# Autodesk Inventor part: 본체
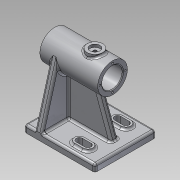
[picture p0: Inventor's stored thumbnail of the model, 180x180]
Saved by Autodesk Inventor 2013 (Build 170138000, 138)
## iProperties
Created: 2019-10
Part Number: 본체
Material: 알루미늄 6061
Document SubType Name: Modeling
Designer: hana-cad17
Density: 2.40731 g/cm^3
Mass: 523.177 g
Surface Area: 544.458 cm^2
Volume: 217.328 cm^3
Author: hana-cad17
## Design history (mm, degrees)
sketch "스케치1"
  geometry: L1 (-50, 43)-(50, 43); L2 (50, 43)-(50, -43); L3 (50, -43)-(-50, -43); L4 (-50, -43)-(-50, 43); 3 further points
  constraints: 8 end point, 2 midpoint, 2 parallel, 1 horizontal, 1 horizontal alignment, 1 perpendicular, 1 vertical alignment
  dimensions: "d0" = 100 distance of L1.start L1.end; "d2" = 86 distance of L3.end L1.start
extrude "돌출1" new body sketch "스케치1" distance "d3" = 10; taper "d4" = 0 deg
sketch "스케치2"
  geometry: L1 (-32, 86)-(50, 86); L2 (50, 0)-(-50, 0) reference; L3 (-32, 86)-(-32, 107); L4 (-32, 107)-(50, 107); L5 (50, 107)-(50, 86); L6 (50, 0)-(50, 10) reference; 2 further points
  constraints: 8 end point, 2 perpendicular, 1 horizontal, 1 midpoint, 1 parallel, 1 vertical alignment
  dimensions: "d5" = 82 distance of L1.start L1.end; "d7" = 86 distance from line of L1.end L2; "d8" = 42 diameter of L4 L1
revolve "회전1" sketch "스케치2" stored, may be unused: angle "d9" = 90 deg
sketch "스케치4"
  geometry: L1 (50, 65)-(50, 107) reference; L2 (-32, 65)-(-32, 107) reference; L3 (-32, 86)-(50, 86); L4 (-32, 100.5)-(30, 100.5); L5 (30, 100.5)-(30, 97.5); L6 (30, 97.5)-(50, 97.5); 1 further point
  constraints: 8 end point, 2 midpoint, 2 parallel, 2 point on line, 1 perpendicular
  dimensions: "d11" = 23 diameter of L6 L3; "d13" = 29 diameter of L4 L3; "d14" = 62 distance of L4.start L4.end
revolve "회전2" sketch "스케치4" stored, may be unused: angle "d15" = 90 deg
node "작업 평면1"
sketch "스케치6"
  geometry: L1 (0, 86)-(10, 86) reference; L2 (10, 86)-(10, 0) reference; L3 (10, 0)-(0, 0) reference; L4 (0, 0)-(0, 86) reference; L5 (10, 86)-(91.642, 63.228); L6 (10, 0)-(91.642, 22.772); C1 r 11.5 at (86, 43) reference; A1 r 21 centre (86, 43) between (91.642, 63.228) and (91.642, 22.772) reference; 1 further point
  constraints: 4 end point, 2 point on circle, 2 tangent
extrude "돌출2" join sketch "스케치6" distance "d19" = 10; taper "d20" = 0 deg
sketch "스케치7"
  geometry: L1 (50, 97.5)-(30, 97.5) reference; L2 (30, 97.5)-(30, 100.5) reference; L3 (30, 100.5)-(-32, 100.5) reference; L4 (-32, 100.5)-(-32, 107) reference; L5 (-32, 107)-(50, 107) reference; L6 (50, 107)-(50, 97.5) reference; L7 (-50, 0)-(-50, 10) reference; L8 (-50, 10)-(25, 10) reference; L9 (25, 10)-(25, 65) reference; L10 (25, 65)-(-32, 65) reference; L11 (-32, 65)-(-32, 71.5) reference; L12 (-32, 71.5)-(30, 71.5) reference; L13 (30, 71.5)-(30, 74.5) reference; L14 (30, 74.5)-(50, 74.5) reference; L15 (50, 74.5)-(50, 65) reference; L16 (50, 65)-(35, 65) reference; L17 (35, 65)-(35, 10) reference; L18 (35, 10)-(50, 10) reference; L19 (50, 10)-(50, 0) reference; L20 (50, 0)-(-50, 0) reference; L21 (-35, 10)-(-14.982, 65); 1 further point
  constraints: 2 end point, 2 point on line
  dimensions: "d21" = 70 deg angle of L21 L8; "d22" = 15 distance of L7.end L21.start
feature "리브1" sketch "스케치7" dims "d23" = 1, "d24" = 10, "d25" = 0, "d26" = 0, "d27" = 1, "d28" = 1
sketch "스케치8"
  geometry: L1 (50, -43)-(50, 43) reference; L2 (24, 20)-(12, 20); L3 (24, 34)-(12, 34); A1 r 7 centre (24, 27) between (24, 20) and (24, 34); A2 r 7 centre (12, 27) between (12, 34) and (12, 20); 1 further point
  constraints: 4 end point, 4 point on circle, 4 tangent, 2 centre point, 1 equal radius, 1 horizontal alignment
  dimensions: "d29" = 27 vertical distance of A1.centre point (0, 0); "d30" = 14 diameter of A1; "d31" = 12 distance of A2.centre A1.centre; "d32" = 26 distance from line of A1.centre L1
extrude "돌출3" join sketch "스케치8" distance "d33" = 3; taper "d34" = 0 deg
sketch "스케치9"
  geometry: L1 (24, 34)-(12, 34) reference; L2 (12, 20)-(24, 20) reference; L3 (12, 31.5)-(24, 31.5); L4 (24, 22.5)-(12, 22.5); A1 r 7 centre (24, 27) between (24, 20) and (24, 34) reference; A2 r 7 centre (12, 27) between (12, 34) and (12, 20) reference; A3 r 4.5 centre (24, 27) between (24, 22.5) and (24, 31.5); A4 r 4.5 centre (12, 27) between (12, 31.5) and (12, 22.5); 1 further point
  constraints: 4 end point, 4 point on circle, 2 centre point, 3 other
  dimensions: "d35" = 4.5 radius of A3
extrude "돌출4" cut sketch "스케치9" stored distance "d38" = 10; taper "d39" = 0 deg
node "작업 평면2"
sketch "스케치10"
  geometry: L1 (-32, -21)-(-32, 21) reference; C1 r 11 at (-7, 0); 1 further point
  constraints: 1 centre point, 1 horizontal alignment
  dimensions: "d41" = 22 diameter of C1; "d43" = 25 distance from line of L1 C1.centre
extrude "돌출5" join sketch "스케치10" stored distance "d44" = 10; taper "d45" = 0 deg
sketch "스케치11"
  geometry: C1 r 11 at (0, 0) reference; C2 r 7 at (0, 0); 1 further point
  constraints: 1 centre point, 1 coincident
  dimensions: "d46" = 14 diameter of C2
extrude "돌출6" cut sketch "스케치11" distance "d48" = 4; taper "d49" = 0 deg
sketch "스케치12"
  geometry: 2 further points
  constraints: 1 horizontal alignment
hole "구멍1" sketch "스케치12" at (0, 0) diameter "d50" = 4.917; stored, may be unused: countersink angle "d54" = 90 deg, drill point angle "d56" = 118 deg; dims "d51" = 6, "d52" = 4, "d53" = 2, "d55" = 8
sketch "스케치13"
  geometry: C1 r 11.5 at (0, 0) reference; 2 further points
  constraints: 1 vertical alignment
  dimensions: "d57" = 18 distance of point (0, -18) C1.centre
hole "구멍2" sketch "스케치13" at (0, -18) diameter "d58" = 2.459; stored, may be unused: countersink angle "d62" = 90 deg, drill point angle "d64" = 118 deg; dims "d59" = 8, "d60" = 4, "d61" = 2, "d63" = 10
sketch "스케치14"
  geometry: C1 r 14.5 at (0, 0) reference; 2 further points
  constraints: 1 vertical alignment
  dimensions: "d68" = 18 distance of C1.centre point (0, 18)
hole "구멍3" sketch "스케치14" at (0, 18) diameter "d69" = 2.459; stored, may be unused: countersink angle "d73" = 90 deg, drill point angle "d75" = 118 deg; dims "d70" = 8, "d71" = 4, "d72" = 2, "d74" = 10
fillet "모깎기1" dims "d79" = 3
fillet "모깎기2" dims "d80" = 3
fillet "모깎기3" dims "d81" = 3
fillet "모깎기4" dims "d82" = 3
fillet "모깎기5" dims "d83" = 3
fillet "모깎기6" dims "d84" = 3
fillet "모깎기7" dims "d85" = 3
chamfer "모따기1" distance "d86" = 1; stored, may be unused: second distance "d87" = 2, angle "d88" = 45 deg
node "작업 평면3"
sketch "스케치16"
  geometry: L1 (-50, 40)-(-50, -40) reference; 2 further points
  constraints: 1 horizontal alignment, 1 other
  dimensions: "d90" = 7 distance from line of point (-43, 0) L1
feature "엠보싱1" sketch "스케치16" dims "d0" = 100, "d2" = 86, "d91" = 0.5, "d92" = 0
fillet "모깎기8" dims "d93" = 3
node "솔리드1"
mirror "대칭1"
pattern_circular "원형 패턴1" dims angle "d66" = 360 deg
pattern_circular "원형 패턴2" dims angle "d77" = 360 deg
node "투영된 루프1"
node "절단 모서리 투영1"
node "절단 모서리 투영2"
other parameters: "d18" = -15, "d89" = 15
